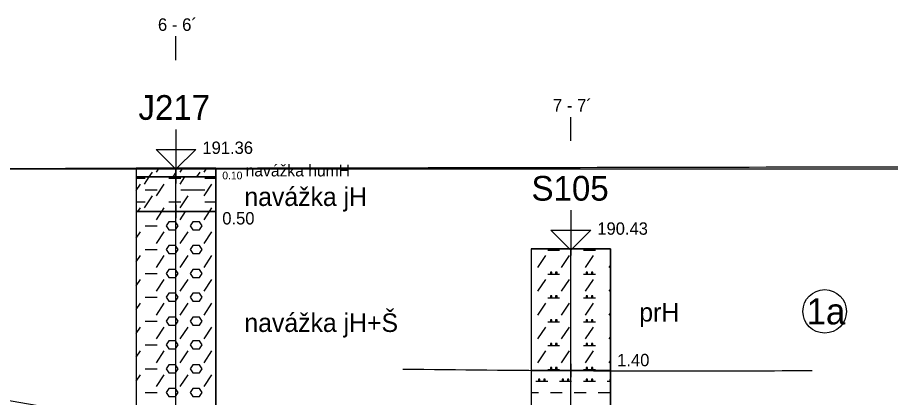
# Model space of a CAD drawing. Extents: x 3042 to 4120, y 576 to 2694.
# Drawn here: x 3548.2 to 3598.4, y 903.5 to 925.3 of the extents above; entities that cross this region are included whole.
import ezdxf

# ---------------------------------------------------------------- set-up
doc = ezdxf.new("R2010")
doc.units = 0
for name, color, linetype in [('15', 7, 'Continuous'), ('16', 7, 'Continuous'), ('17', 7, 'Continuous'), ('18', 7, 'Continuous'), ('22', 7, 'Continuous'), ('51', 7, 'Continuous'), ('52', 7, 'Continuous'), ('53', 7, 'Continuous'), ('56', 7, 'Continuous'), ('pomocna', 7, 'Continuous'), ('rozhraní', 7, 'Continuous')]:
    doc.layers.add(name, color=color, linetype=linetype)

msp = doc.modelspace()

# ---------------------------------------------------------------- linework, layer by layer
at = {"layer": '15'}
for points in [[(3557.332, 918.882), (3557.332, 916.596), (3556.189, 917.739), (3558.475, 917.739), (3557.332, 916.596)], [(3580.052, 914.232), (3580.052, 911.946), (3578.909, 913.089), (3581.195, 913.089), (3580.052, 911.946)]]:
    msp.add_lwpolyline(points, dxfattribs=at)
at = {"layer": '18'}
for p, q in [((3557.332, 876.659), (3557.332, 916.659)), ((3580.052, 872.009), (3580.052, 912.009))]:
    msp.add_line(p, q, dxfattribs=at)
at = {"layer": '22'}
for points in [[(3557.332, 922.882), (3557.332, 922.882), (3557.332, 924.251)], [(3580.052, 918.232), (3580.052, 918.232), (3580.052, 919.601)]]:
    msp.add_lwpolyline(points, dxfattribs=at)
at = {"layer": '51'}
for p, q in [((3555.795, 916.159), (3555.975, 916.43)), ((3556.204, 916.43), (3556.357, 916.659)), ((3557.166, 916.159), (3557.347, 916.43)), ((3557.576, 916.43), (3557.728, 916.659)), ((3558.538, 916.159), (3558.719, 916.43)), ((3558.947, 916.43), (3559.1, 916.659)), ((3555.046, 916.087), (3555.556, 916.087)), ((3555.046, 915.378), (3555.29, 915.744)), ((3555.518, 915.744), (3555.795, 916.159)), ((3556.204, 915.058), (3556.661, 915.744)), ((3556.928, 916.087), (3557.614, 916.087)), ((3557.576, 915.744), (3557.852, 916.159)), ((3558.947, 915.058), (3559.404, 915.744)), ((3558.985, 916.087), (3559.618, 916.087)), ((3555.556, 915.401), (3556.242, 915.401)), ((3557.614, 915.401), (3558.3, 915.401)), ((3558.3, 915.401), (3558.985, 915.401)), ((3555.046, 914.716), (3555.556, 914.716)), ((3555.518, 914.373), (3555.975, 915.058)), ((3556.928, 914.716), (3557.614, 914.716)), ((3557.576, 914.373), (3558.033, 915.058)), ((3558.985, 914.716), (3559.618, 914.716)), ((3555.147, 914.159), (3555.29, 914.373)), ((3556.519, 914.159), (3556.661, 914.373)), ((3559.262, 914.159), (3559.404, 914.373)), ((3556.204, 913.687), (3556.519, 914.159)), ((3557.576, 913.687), (3557.89, 914.159)), ((3558.947, 913.687), (3559.262, 914.159)), ((3555.556, 913.344), (3556.242, 913.344)), ((3555.046, 912.635), (3555.29, 913.001)), ((3556.204, 912.315), (3556.661, 913.001)), ((3557.576, 912.315), (3558.033, 913.001)), ((3558.947, 912.315), (3559.404, 913.001)), ((3555.556, 911.972), (3556.242, 911.972)), ((3578.721, 911.934), (3579.407, 911.934)), ((3578.913, 912.009), (3578.95, 911.972)), ((3579.218, 912.009), (3579.255, 911.972)), ((3580.779, 911.934), (3581.464, 911.934)), ((3580.97, 912.009), (3581.007, 911.972)), ((3581.275, 912.009), (3581.312, 911.972)), ((3555.046, 911.264), (3555.29, 911.629)), ((3556.204, 910.944), (3556.661, 911.629)), ((3557.576, 910.944), (3558.033, 911.629)), ((3558.947, 910.944), (3559.404, 911.629)), ((3578.15, 910.944), (3578.607, 911.629)), ((3579.521, 910.944), (3579.978, 911.629)), ((3580.893, 910.944), (3581.35, 911.629)), ((3582.264, 910.944), (3582.338, 911.053)), ((3555.046, 909.892), (3555.29, 910.258)), ((3555.556, 910.601), (3556.242, 910.601)), ((3556.204, 909.572), (3556.661, 910.258)), ((3557.576, 909.572), (3558.033, 910.258)), ((3558.947, 909.572), (3559.404, 910.258)), ((3578.15, 909.572), (3578.607, 910.258)), ((3578.721, 910.563), (3579.407, 910.563)), ((3579.521, 909.572), (3579.978, 910.258)), ((3580.779, 910.563), (3581.464, 910.563)), ((3580.893, 909.572), (3581.35, 910.258)), ((3582.264, 909.572), (3582.338, 909.682)), ((3555.556, 909.229), (3556.242, 909.229)), ((3578.721, 909.191), (3579.407, 909.191)), ((3580.779, 909.191), (3581.464, 909.191)), ((3555.046, 908.52), (3555.29, 908.886)), ((3556.204, 908.2), (3556.661, 908.886)), ((3557.576, 908.2), (3558.033, 908.886)), ((3558.947, 908.2), (3559.404, 908.886)), ((3578.15, 908.2), (3578.607, 908.886)), ((3579.521, 908.2), (3579.978, 908.886)), ((3580.893, 908.2), (3581.35, 908.886)), ((3582.264, 908.2), (3582.338, 908.31)), ((3555.556, 907.858), (3556.242, 907.858)), ((3578.721, 907.819), (3579.407, 907.819)), ((3580.779, 907.819), (3581.464, 907.819)), ((3555.046, 907.149), (3555.29, 907.515)), ((3556.204, 906.829), (3556.661, 907.515)), ((3557.576, 906.829), (3558.033, 907.515)), ((3558.947, 906.829), (3559.404, 907.515)), ((3578.15, 906.829), (3578.607, 907.515)), ((3579.521, 906.829), (3579.978, 907.515)), ((3580.893, 906.829), (3581.35, 907.515)), ((3582.264, 906.829), (3582.338, 906.939)), ((3555.556, 906.486), (3556.242, 906.486)), ((3578.721, 906.448), (3579.407, 906.448)), ((3580.779, 906.448), (3581.464, 906.448)), ((3555.046, 905.777), (3555.29, 906.143)), ((3556.204, 905.457), (3556.661, 906.143)), ((3557.576, 905.457), (3558.033, 906.143)), ((3558.947, 905.457), (3559.404, 906.143)), ((3578.15, 905.457), (3578.607, 906.143)), ((3579.521, 905.457), (3579.978, 906.143)), ((3580.893, 905.457), (3581.35, 906.143)), ((3582.264, 905.457), (3582.338, 905.567)), ((3555.046, 904.406), (3555.29, 904.771)), ((3555.556, 905.114), (3556.242, 905.114)), ((3556.204, 904.086), (3556.661, 904.771)), ((3557.576, 904.086), (3558.033, 904.771)), ((3558.947, 904.086), (3559.404, 904.771)), ((3578.721, 905.076), (3579.407, 905.076)), ((3580.779, 905.076), (3581.464, 905.076)), ((3578.035, 904.39), (3578.721, 904.39)), ((3579.407, 904.39), (3580.093, 904.39)), ((3580.779, 904.39), (3581.464, 904.39)), ((3582.15, 904.39), (3582.338, 904.39)), ((3555.556, 903.743), (3556.242, 903.743)), ((3577.766, 903.743), (3578.188, 903.743)), ((3578.874, 903.743), (3579.559, 903.743)), ((3580.245, 903.743), (3580.931, 903.743)), ((3581.617, 903.743), (3582.303, 903.743))]:
    msp.add_line(p, q, dxfattribs=at)
for points in [[(3555.046, 916.159), (3559.618, 916.159), (3559.618, 916.659), (3555.046, 916.659)], [(3555.046, 914.159), (3559.618, 914.159), (3559.618, 916.159), (3555.046, 916.159)], [(3555.046, 901.659), (3559.618, 901.659), (3559.618, 914.159), (3555.046, 914.159)], [(3577.766, 905.009), (3582.338, 905.009), (3582.338, 912.009), (3577.766, 912.009)], [(3577.766, 900.509), (3582.338, 900.509), (3582.338, 905.009), (3577.766, 905.009)]]:
    msp.add_lwpolyline(points, close=True, dxfattribs=at)
for points in [[(3556.928, 913.115), (3557.309, 913.115), (3557.461, 913.344), (3557.309, 913.573), (3556.928, 913.573), (3556.776, 913.344), (3556.928, 913.115)], [(3558.3, 913.115), (3558.681, 913.115), (3558.833, 913.344), (3558.681, 913.573), (3558.3, 913.573), (3558.147, 913.344), (3558.3, 913.115)], [(3556.928, 911.744), (3557.309, 911.744), (3557.461, 911.972), (3557.309, 912.201), (3556.928, 912.201), (3556.776, 911.972), (3556.928, 911.744)], [(3558.3, 911.744), (3558.681, 911.744), (3558.833, 911.972), (3558.681, 912.201), (3558.3, 912.201), (3558.147, 911.972), (3558.3, 911.744)], [(3578.874, 912.009), (3578.874, 911.972), (3578.95, 911.972), (3578.95, 912.009)], [(3579.178, 912.009), (3579.178, 911.972), (3579.255, 911.972), (3579.255, 912.009)], [(3580.931, 912.009), (3580.931, 911.972), (3581.007, 911.972), (3581.007, 912.009)], [(3581.236, 912.009), (3581.236, 911.972), (3581.312, 911.972), (3581.312, 912.009)], [(3556.928, 910.372), (3557.309, 910.372), (3557.461, 910.601), (3557.309, 910.829), (3556.928, 910.829), (3556.776, 910.601), (3556.928, 910.372)], [(3558.3, 910.372), (3558.681, 910.372), (3558.833, 910.601), (3558.681, 910.829), (3558.3, 910.829), (3558.147, 910.601), (3558.3, 910.372)], [(3578.874, 910.677), (3578.874, 910.601), (3578.95, 910.601), (3578.95, 910.677), (3578.874, 910.677), (3578.95, 910.601)], [(3579.178, 910.677), (3579.178, 910.601), (3579.255, 910.601), (3579.255, 910.677), (3579.178, 910.677), (3579.255, 910.601)], [(3580.931, 910.677), (3580.931, 910.601), (3581.007, 910.601), (3581.007, 910.677), (3580.931, 910.677), (3581.007, 910.601)], [(3581.236, 910.677), (3581.236, 910.601), (3581.312, 910.601), (3581.312, 910.677), (3581.236, 910.677), (3581.312, 910.601)], [(3556.928, 909.001), (3557.309, 909.001), (3557.461, 909.229), (3557.309, 909.458), (3556.928, 909.458), (3556.776, 909.229), (3556.928, 909.001)], [(3558.3, 909.001), (3558.681, 909.001), (3558.833, 909.229), (3558.681, 909.458), (3558.3, 909.458), (3558.147, 909.229), (3558.3, 909.001)], [(3578.874, 909.305), (3578.874, 909.229), (3578.95, 909.229), (3578.95, 909.305), (3578.874, 909.305), (3578.95, 909.229)], [(3579.178, 909.305), (3579.178, 909.229), (3579.255, 909.229), (3579.255, 909.305), (3579.178, 909.305), (3579.255, 909.229)], [(3580.931, 909.305), (3580.931, 909.229), (3581.007, 909.229), (3581.007, 909.305), (3580.931, 909.305), (3581.007, 909.229)], [(3581.236, 909.305), (3581.236, 909.229), (3581.312, 909.229), (3581.312, 909.305), (3581.236, 909.305), (3581.312, 909.229)], [(3556.928, 907.629), (3557.309, 907.629), (3557.461, 907.858), (3557.309, 908.086), (3556.928, 908.086), (3556.776, 907.858), (3556.928, 907.629)], [(3558.3, 907.629), (3558.681, 907.629), (3558.833, 907.858), (3558.681, 908.086), (3558.3, 908.086), (3558.147, 907.858), (3558.3, 907.629)], [(3578.874, 907.934), (3578.874, 907.858), (3578.95, 907.858), (3578.95, 907.934), (3578.874, 907.934), (3578.95, 907.858)], [(3579.178, 907.934), (3579.178, 907.858), (3579.255, 907.858), (3579.255, 907.934), (3579.178, 907.934), (3579.255, 907.858)], [(3580.931, 907.934), (3580.931, 907.858), (3581.007, 907.858), (3581.007, 907.934), (3580.931, 907.934), (3581.007, 907.858)], [(3581.236, 907.934), (3581.236, 907.858), (3581.312, 907.858), (3581.312, 907.934), (3581.236, 907.934), (3581.312, 907.858)], [(3556.928, 906.257), (3557.309, 906.257), (3557.461, 906.486), (3557.309, 906.715), (3556.928, 906.715), (3556.776, 906.486), (3556.928, 906.257)], [(3558.3, 906.257), (3558.681, 906.257), (3558.833, 906.486), (3558.681, 906.715), (3558.3, 906.715), (3558.147, 906.486), (3558.3, 906.257)], [(3578.874, 906.562), (3578.874, 906.486), (3578.95, 906.486), (3578.95, 906.562), (3578.874, 906.562), (3578.95, 906.486)], [(3579.178, 906.562), (3579.178, 906.486), (3579.255, 906.486), (3579.255, 906.562), (3579.178, 906.562), (3579.255, 906.486)], [(3580.931, 906.562), (3580.931, 906.486), (3581.007, 906.486), (3581.007, 906.562), (3580.931, 906.562), (3581.007, 906.486)], [(3581.236, 906.562), (3581.236, 906.486), (3581.312, 906.486), (3581.312, 906.562), (3581.236, 906.562), (3581.312, 906.486)], [(3556.928, 904.886), (3557.309, 904.886), (3557.461, 905.114), (3557.309, 905.343), (3556.928, 905.343), (3556.776, 905.114), (3556.928, 904.886)], [(3558.3, 904.886), (3558.681, 904.886), (3558.833, 905.114), (3558.681, 905.343), (3558.3, 905.343), (3558.147, 905.114), (3558.3, 904.886)], [(3578.874, 905.191), (3578.874, 905.114), (3578.95, 905.114), (3578.95, 905.191), (3578.874, 905.191), (3578.95, 905.114)], [(3579.178, 905.191), (3579.178, 905.114), (3579.255, 905.114), (3579.255, 905.191), (3579.178, 905.191), (3579.255, 905.114)], [(3580.931, 905.191), (3580.931, 905.114), (3581.007, 905.114), (3581.007, 905.191), (3580.931, 905.191), (3581.007, 905.114)], [(3581.236, 905.191), (3581.236, 905.114), (3581.312, 905.114), (3581.312, 905.191), (3581.236, 905.191), (3581.312, 905.114)], [(3578.188, 904.505), (3578.188, 904.429), (3578.264, 904.429), (3578.264, 904.505), (3578.188, 904.505), (3578.264, 904.429)], [(3578.493, 904.505), (3578.493, 904.429), (3578.569, 904.429), (3578.569, 904.505), (3578.493, 904.505), (3578.569, 904.429)], [(3579.559, 904.505), (3579.559, 904.429), (3579.636, 904.429), (3579.636, 904.505), (3579.559, 904.505), (3579.636, 904.429)], [(3579.864, 904.505), (3579.864, 904.429), (3579.94, 904.429), (3579.94, 904.505), (3579.864, 904.505), (3579.94, 904.429)], [(3580.931, 904.505), (3580.931, 904.429), (3581.007, 904.429), (3581.007, 904.505), (3580.931, 904.505), (3581.007, 904.429)], [(3581.236, 904.505), (3581.236, 904.429), (3581.312, 904.429), (3581.312, 904.505), (3581.236, 904.505), (3581.312, 904.429)], [(3582.303, 904.505), (3582.303, 904.429), (3582.338, 904.429)], [(3582.338, 904.505), (3582.303, 904.505), (3582.338, 904.47)], [(3556.928, 903.514), (3557.309, 903.514), (3557.461, 903.743), (3557.309, 903.971), (3556.928, 903.971), (3556.776, 903.743), (3556.928, 903.514)], [(3558.3, 903.514), (3558.681, 903.514), (3558.833, 903.743), (3558.681, 903.971), (3558.3, 903.971), (3558.147, 903.743), (3558.3, 903.514)]]:
    msp.add_lwpolyline(points, dxfattribs=at)
at = {"layer": '53'}
for p, q in [((3555.046, 916.659), (3555.046, 876.659)), ((3555.046, 916.659), (3559.618, 916.659)), ((3559.618, 916.659), (3559.618, 876.659)), ((3555.046, 916.159), (3559.618, 916.159)), ((3555.046, 914.159), (3559.618, 914.159)), ((3577.766, 912.009), (3582.338, 912.009)), ((3577.766, 912.009), (3577.766, 872.009)), ((3582.338, 912.009), (3582.338, 872.009)), ((3577.766, 905.009), (3582.338, 905.009))]:
    msp.add_line(p, q, dxfattribs=at)
at = {"layer": '56'}
for p, q in [((3557.332, 917.04), (3557.332, 916.278)), ((3556.951, 916.659), (3557.713, 916.659)), ((3557.332, 916.54), (3557.332, 915.778)), ((3556.951, 916.159), (3557.713, 916.159)), ((3557.332, 914.54), (3557.332, 913.778)), ((3556.951, 914.159), (3557.713, 914.159)), ((3580.052, 912.39), (3580.052, 911.628)), ((3579.671, 912.009), (3580.433, 912.009)), ((3580.052, 905.39), (3580.052, 904.628)), ((3579.671, 905.009), (3580.433, 905.009))]:
    msp.add_line(p, q, dxfattribs=at)
at = {"layer": 'pomocna'}
msp.add_line((3641.132, 916.609), (3515.508, 916.609), dxfattribs=at)
at = {"layer": 'rozhraní'}
msp.add_circle((3594.655, 908.416), 1.25, dxfattribs=at)
for points in [[(3523.722, 916.609), (3557.268, 916.659), (3619.463, 916.759), (3636.136, 916.759)], [(3507.468, 910.407), (3557.332, 901.659), (3619.082, 894.759), (3631.6, 894.759)], [(3570.391, 905.094), (3580.052, 905.009), (3593.937, 905.009)]]:
    msp.add_spline(points, degree=3, dxfattribs=at)

# ---------------------------------------------------------------- texts
at = {"layer": '16'}
for s, p in [('J217', (3555.173, 919.438)), ('S105', (3577.787, 914.788))]:
    msp.add_text(s, height=1.4224, dxfattribs=at).set_placement(p)
at = {"layer": '17'}
for s, p in [('191.36', (3558.856, 917.477)), ('190.43', (3581.576, 912.827))]:
    msp.add_text(s, height=0.7112, dxfattribs=at).set_placement(p)
at = {"layer": '22'}
for s, p in [('6 - 6´', (3556.296, 924.56)), ('7 - 7´', (3579.016, 919.91))]:
    msp.add_text(s, height=0.72, dxfattribs=at).set_placement(p)
at = {"layer": '52'}
for s, height, p in [('navážka humH', 0.6731, (3561.341, 916.182)), ('0.10', 0.4445, (3559.999, 916.013)), ('navážka jH', 1.0668, (3561.269, 914.481)), ('0.50', 0.7112, (3559.999, 913.417)), ('prH', 1.0668, (3583.989, 907.831)), ('navážka jH+Š', 1.0668, (3561.269, 907.231)), ('1.40', 0.7112, (3582.719, 905.26))]:
    msp.add_text(s, height=height, dxfattribs=at).set_placement(p)
at = {"layer": 'rozhraní'}
msp.add_text('1a', height=1.5, dxfattribs=at).set_placement((3593.611, 907.666))

doc.saveas('drawing.dxf')
